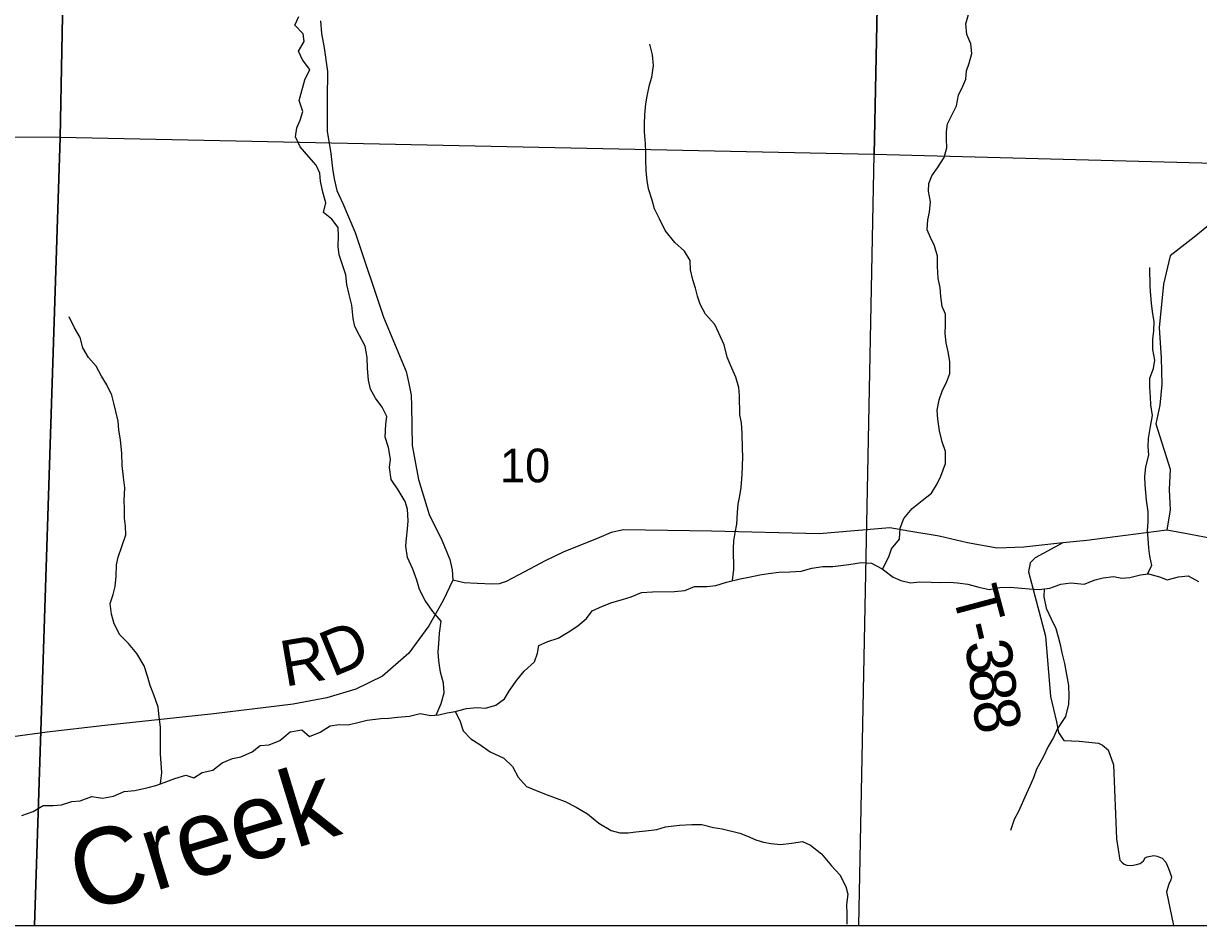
# Model space of a CAD drawing. Extents: x -3.6 to 34, y 0 to 32.8.
# Drawn here: x -1.871 to -0.41, y 26.043 to 27.165 of the extents above; entities that cross this region are included whole.
import ezdxf

# ---------------------------------------------------------------- set-up
doc = ezdxf.new("R2010")
doc.units = 0
for name, color, linetype in [('GM_X_Corporation', 7, 'Continuous'), ('GM_X_County_Road', 7, 'Continuous'), ('GM_X_County_Road_Text', 7, 'Continuous'), ('GM_X_Minor_River', 7, 'Continuous'), ('GM_X_Minor_River_Text', 7, 'Continuous'), ('GM_X_Section_Text', 7, 'Continuous'), ('GM_X_Township_Road', 7, 'Continuous'), ('GM_X_Township_Road_Text', 7, 'Continuous'), ('SH_Data', 7, 'Continuous')]:
    doc.layers.add(name, color=color, linetype=linetype)

msp = doc.modelspace()

# ---------------------------------------------------------------- linework, layer by layer
at = {"layer": 'GM_X_Corporation'}
for points in [[(3.1705, 28.9337), (3.1705, 32.8429), (-3.6295, 32.8429), (-3.6295, 26.0429), (2.3706, 26.0429), (2.3712, 26.0804), (2.3716, 26.1248), (2.3732, 26.2253), (2.3789, 26.6097), (2.3911, 27.5117), (2.3952, 27.9336), (2.3997, 28.282), (2.4082, 28.9473), (2.5416, 28.945), (2.5837, 28.9442), (2.8343, 28.9397)], [(-1.8056, 28.0368), (-1.8251, 27.0226), (-2.8456, 27.0298), (-2.8264, 28.0607)], [(-0.7925, 28.0131), (-0.8131, 27.0015), (-1.8251, 27.0226), (-1.8056, 28.0368)], [(-0.7925, 28.0131), (0.2336, 27.9902), (0.2053, 26.9746), (-0.8131, 27.0015)], [(-2.8578, 26.0429), (-1.8572, 26.0429), (-1.8251, 27.0226), (-2.8456, 27.0298)], [(-1.8572, 26.0429), (-0.8324, 26.0429), (-0.8131, 27.0015), (-1.8251, 27.0226)]]:
    msp.add_lwpolyline(points, close=True, dxfattribs=at)
msp.add_lwpolyline([(-0.398, 30.5946), (-0.453, 30.5952), (-0.5034, 30.5954), (-2.3541, 30.6318), (-2.7027, 30.634), (-2.8007, 30.6338), (-2.8012, 30.524), (-2.8047, 30.129), (-2.8073, 29.6484), (-2.813, 28.9119), (-2.8208, 28.0589), (-2.8426, 27.1), (-2.8499, 26.4099), (-2.8635, 26.0429), (2.3706, 26.0429)], dxfattribs=at)
at = {"layer": 'GM_X_County_Road'}
msp.add_lwpolyline([(-1.5014, 27.168), (-1.5002, 27.152), (-1.4969, 27.1342), (-1.4928, 27.105), (-1.4934, 27.0712), (-1.4934, 27.044), (-1.4932, 27.0308), (-1.4887, 27.003), (-1.4867, 26.9844), (-1.4847, 26.9713), (-1.4811, 26.957), (-1.4737, 26.9406), (-1.4582, 26.9046), (-1.4232, 26.7992), (-1.3951, 26.7317), (-1.3916, 26.7167), (-1.3889, 26.7025), (-1.3885, 26.6889), (-1.3875, 26.6396), (-1.3797, 26.5974), (-1.3665, 26.554), (-1.3503, 26.5214), (-1.3406, 26.4982), (-1.3378, 26.485), (-1.3369, 26.4723), (-1.3491, 26.447), (-1.3667, 26.4157), (-1.3915, 26.3814), (-1.4244, 26.353), (-1.4574, 26.3366), (-1.4937, 26.3258), (-1.5355, 26.3181), (-1.6342, 26.306), (-1.7694, 26.2915), (-1.8412, 26.2831), (-1.8841, 26.2773)], dxfattribs=at)
at = {"layer": 'GM_X_Minor_River'}
for points in [[(-0.7085, 27.0754), (-0.7029, 27.0868), (-0.6995, 27.0953), (-0.6985, 27.1055), (-0.6953, 27.1154), (-0.692, 27.1273), (-0.6933, 27.1394), (-0.6981, 27.1507), (-0.6994, 27.164), (-0.6951, 27.1785), (-0.6922, 27.1918), (-0.6955, 27.2066), (-0.7006, 27.2183), (-0.703, 27.2323), (-0.6975, 27.2453), (-0.694, 27.259), (-0.7009, 27.2709), (-0.7109, 27.2783)], [(-1.3576, 26.3046), (-1.3517, 26.319), (-1.3477, 26.3323), (-1.3487, 26.3441), (-1.3523, 26.3581), (-1.3544, 26.3721), (-1.3554, 26.3827), (-1.3544, 26.3937), (-1.3535, 26.4066), (-1.3515, 26.4215), (-1.3619, 26.4334), (-1.3712, 26.4469), (-1.3786, 26.4608), (-1.3818, 26.4722), (-1.3866, 26.4858), (-1.3933, 26.5004), (-1.3954, 26.5145), (-1.3944, 26.524), (-1.3935, 26.5357), (-1.3925, 26.546), (-1.3935, 26.5604), (-1.3963, 26.5702), (-1.4049, 26.5845), (-1.4138, 26.5973), (-1.4159, 26.6124), (-1.4146, 26.6227), (-1.4171, 26.6374), (-1.4211, 26.6503), (-1.4202, 26.6662), (-1.4192, 26.6757), (-1.4247, 26.6874), (-1.4333, 26.6987), (-1.4395, 26.7099), (-1.4419, 26.7209), (-1.4429, 26.7357), (-1.4435, 26.749), (-1.4461, 26.7633), (-1.4531, 26.7765), (-1.4589, 26.7878), (-1.461, 26.7976), (-1.4624, 26.8143), (-1.466, 26.8275), (-1.4689, 26.84), (-1.4702, 26.8518), (-1.4738, 26.8631), (-1.4782, 26.877), (-1.4795, 26.8873), (-1.479, 26.9006), (-1.4795, 26.9108), (-1.4873, 26.9213), (-1.4976, 26.9295), (-1.4948, 26.9417), (-1.4988, 26.9549), (-1.5013, 26.9685), (-1.5022, 26.9784), (-1.5069, 26.9885), (-1.5158, 26.9986), (-1.5266, 27.011), (-1.5325, 27.0234), (-1.5308, 27.0348), (-1.5268, 27.0444), (-1.5235, 27.055), (-1.5279, 27.0686), (-1.5208, 27.0946), (-1.5149, 27.1072), (-1.5238, 27.1195), (-1.5289, 27.1301), (-1.522, 27.142), (-1.5229, 27.1518), (-1.5333, 27.1623), (-1.5285, 27.1734)], [(-0.9894, 26.4718), (-0.9876, 26.4857), (-0.9881, 26.5115), (-0.9878, 26.5214), (-0.9861, 26.5313), (-0.984, 26.542), (-0.9831, 26.5564), (-0.9825, 26.5667), (-0.9801, 26.5773), (-0.9787, 26.5876), (-0.9775, 26.6039), (-0.9769, 26.6142), (-0.9767, 26.626), (-0.9769, 26.6358), (-0.9772, 26.6552), (-0.9782, 26.6681), (-0.9802, 26.6779), (-0.9806, 26.7018), (-0.9815, 26.7117), (-0.9851, 26.7249), (-0.9902, 26.7358), (-0.9958, 26.7498), (-0.9998, 26.7649), (-1.0065, 26.7796), (-1.0112, 26.7901), (-1.0228, 26.8032), (-1.0294, 26.8156), (-1.033, 26.8254), (-1.0354, 26.8356), (-1.0386, 26.8458), (-1.0415, 26.8583), (-1.042, 26.8697), (-1.049, 26.8813), (-1.0609, 26.8921), (-1.0729, 26.9071), (-1.08, 26.9218), (-1.0862, 26.9342), (-1.0891, 26.9448), (-1.0938, 26.9588), (-1.0955, 26.9694), (-1.0965, 26.9815), (-1.0971, 26.9944), (-1.0969, 27.005), (-1.0974, 27.0149), (-1.0988, 27.03), (-1.0986, 27.0399), (-1.0984, 27.0509), (-1.0971, 27.0646), (-1.0954, 27.0741), (-1.0926, 27.0882), (-1.0897, 27.0978), (-1.0877, 27.1122), (-1.089, 27.1255), (-1.0923, 27.1387)], [(-0.8027, 26.4858), (-0.7952, 26.5015), (-0.7916, 26.5111), (-0.7816, 26.5234), (-0.7811, 26.5371), (-0.7763, 26.5489), (-0.7659, 26.5616), (-0.7536, 26.5713), (-0.742, 26.5806), (-0.735, 26.5921), (-0.7306, 26.6017), (-0.7248, 26.6174), (-0.7247, 26.6322), (-0.7287, 26.6443), (-0.732, 26.6582), (-0.7341, 26.6726), (-0.735, 26.6836), (-0.7326, 26.6966), (-0.7286, 26.7073), (-0.7231, 26.7195), (-0.7191, 26.7291), (-0.7194, 26.7443), (-0.7211, 26.7564), (-0.7239, 26.7673), (-0.7252, 26.7791), (-0.7246, 26.7893), (-0.7245, 26.803), (-0.7288, 26.8128), (-0.7305, 26.8249), (-0.7311, 26.8363), (-0.7336, 26.8476), (-0.7345, 26.8624), (-0.7344, 26.8753), (-0.7384, 26.8882), (-0.7431, 26.8983), (-0.7474, 26.9081), (-0.7465, 26.9203), (-0.7444, 26.9298), (-0.7434, 26.9427), (-0.7456, 26.956), (-0.7453, 26.9655), (-0.7417, 26.975), (-0.7347, 26.985), (-0.7262, 26.9977), (-0.723, 27.0099), (-0.7232, 27.0209), (-0.7233, 27.0304), (-0.722, 27.0399), (-0.7172, 27.0498), (-0.711, 27.0621), (-0.7085, 27.0754)], [(-0.4737, 26.4802), (-0.4682, 26.4907), (-0.4707, 26.502), (-0.472, 26.5122), (-0.4725, 26.524), (-0.4734, 26.5335), (-0.4728, 26.5449), (-0.4726, 26.5574), (-0.4747, 26.5718), (-0.4765, 26.5908), (-0.477, 26.6014), (-0.4757, 26.6132), (-0.4718, 26.6277), (-0.4727, 26.6387), (-0.4724, 26.6486), (-0.4696, 26.6635), (-0.4672, 26.6772), (-0.4693, 26.6904), (-0.4698, 26.7003), (-0.4707, 26.7117), (-0.4705, 26.7235), (-0.4661, 26.7357), (-0.4644, 26.746), (-0.4668, 26.7592), (-0.4667, 26.7721), (-0.4657, 26.7824), (-0.4654, 26.7934), (-0.4671, 26.8063), (-0.4684, 26.8169), (-0.4693, 26.8264), (-0.4702, 26.8374), (-0.4706, 26.861)], [(-1.7002, 26.2193), (-1.6988, 26.2326), (-1.6994, 26.2448), (-1.7004, 26.2561), (-1.7002, 26.2671), (-1.7005, 26.2895), (-1.7019, 26.3024), (-1.7032, 26.3145), (-1.7088, 26.3296), (-1.7131, 26.3413), (-1.7167, 26.353), (-1.7207, 26.3658), (-1.7297, 26.3812), (-1.7401, 26.3936), (-1.7509, 26.4044), (-1.7579, 26.418), (-1.7615, 26.43), (-1.7629, 26.4433), (-1.7593, 26.4544), (-1.7568, 26.4643), (-1.7555, 26.4772), (-1.755, 26.4913), (-1.7529, 26.5008), (-1.7485, 26.5141), (-1.7435, 26.5286), (-1.7437, 26.5396), (-1.745, 26.5495), (-1.7452, 26.5613), (-1.7457, 26.5715), (-1.7448, 26.5871), (-1.7462, 26.6003), (-1.7479, 26.6151), (-1.7486, 26.6303), (-1.7503, 26.6466), (-1.7521, 26.6594), (-1.753, 26.6701), (-1.7559, 26.6821), (-1.7583, 26.6924), (-1.7607, 26.7022), (-1.767, 26.7154), (-1.7736, 26.7259), (-1.7802, 26.7383), (-1.7899, 26.7491), (-1.7969, 26.7612), (-1.8001, 26.774), (-1.8072, 26.786), (-1.8138, 26.7996)], [(-1.5764, 26.2666), (-1.5654, 26.2675), (-1.5519, 26.2731), (-1.5392, 26.2839), (-1.5248, 26.2861), (-1.5152, 26.2779), (-1.5021, 26.2834), (-1.4894, 26.2912), (-1.4784, 26.2929), (-1.467, 26.2924), (-1.4535, 26.2956), (-1.4433, 26.2984), (-1.4267, 26.3003), (-1.4165, 26.3008), (-1.4059, 26.3021), (-1.3908, 26.3031), (-1.3776, 26.3064), (-1.3643, 26.304), (-1.3545, 26.3049), (-1.3439, 26.3074), (-1.3341, 26.309), (-1.3201, 26.3127), (-1.3069, 26.3141), (-1.2963, 26.3131), (-1.2835, 26.3167), (-1.2726, 26.3249), (-1.2664, 26.3349), (-1.2575, 26.3479), (-1.2482, 26.3591), (-1.2356, 26.3707), (-1.2319, 26.3814), (-1.2302, 26.3909), (-1.2189, 26.396), (-1.2061, 26.4), (-1.1938, 26.4078), (-1.1818, 26.4156), (-1.171, 26.4245), (-1.1636, 26.4341), (-1.1508, 26.4401), (-1.1395, 26.4444), (-1.1259, 26.4481), (-1.1154, 26.4517), (-1.1026, 26.4568), (-1.0886, 26.4578), (-1.0614, 26.4583), (-1.0485, 26.4596), (-1.0365, 26.4644), (-1.0214, 26.4643), (-1.01, 26.4656), (-0.9968, 26.47), (-0.9799, 26.4741), (-0.9689, 26.4762), (-0.9554, 26.4791), (-0.9448, 26.4804), (-0.9316, 26.4821), (-0.9183, 26.4827), (-0.904, 26.4837), (-0.8908, 26.4874), (-0.8772, 26.4895), (-0.8647, 26.4893), (-0.8549, 26.4907), (-0.8447, 26.4916), (-0.8292, 26.4941), (-0.8167, 26.4936), (-0.8033, 26.4862), (-0.7895, 26.4762), (-0.78, 26.4718), (-0.7682, 26.469), (-0.7565, 26.4703), (-0.7425, 26.4698), (-0.7323, 26.4696), (-0.7198, 26.4698), (-0.7095, 26.4688), (-0.697, 26.4672)], [(-0.697, 26.4672), (-0.6832, 26.4638), (-0.6703, 26.4606), (-0.657, 26.4631), (-0.6442, 26.4637), (-0.6302, 26.4624), (-0.6207, 26.4614), (-0.6082, 26.4608), (-0.595, 26.4625), (-0.5814, 26.4673), (-0.569, 26.469), (-0.5523, 26.4673), (-0.5384, 26.4729), (-0.5286, 26.4753), (-0.5157, 26.477), (-0.5055, 26.4749), (-0.4953, 26.4758), (-0.4821, 26.4791), (-0.4723, 26.4803), (-0.4586, 26.4764), (-0.4491, 26.4727), (-0.4351, 26.4763), (-0.423, 26.4777), (-0.4101, 26.4707)], [(-0.602, 26.4616), (-0.6024, 26.4514), (-0.5995, 26.4374), (-0.5933, 26.4242), (-0.5874, 26.4121), (-0.5846, 26.4019), (-0.5822, 26.3921), (-0.5798, 26.3819), (-0.5766, 26.3686), (-0.5716, 26.3413), (-0.5711, 26.3281), (-0.5717, 26.3182), (-0.5756, 26.3029), (-0.5852, 26.288), (-0.5904, 26.2765), (-0.597, 26.2654), (-0.6033, 26.2524), (-0.6114, 26.2371), (-0.615, 26.2264), (-0.6198, 26.216), (-0.6245, 26.2061), (-0.634, 26.1847), (-0.6392, 26.1747), (-0.6439, 26.161)], [(-1.3341, 26.309), (-1.3282, 26.2978), (-1.3242, 26.2849), (-1.3146, 26.2748), (-1.3035, 26.2678), (-1.2905, 26.2589), (-1.2737, 26.2509), (-1.2629, 26.2404), (-1.2559, 26.2273), (-1.2455, 26.2157), (-1.2314, 26.2098), (-1.2196, 26.2055), (-1.2085, 26.2011), (-1.1975, 26.1971), (-1.1837, 26.1902), (-1.1696, 26.1817), (-1.1554, 26.1702), (-1.1401, 26.1609), (-1.1294, 26.1581), (-1.1192, 26.1579), (-1.1094, 26.1592), (-1.0973, 26.1605), (-1.0833, 26.1623), (-1.0728, 26.1655), (-1.0554, 26.1677), (-1.0399, 26.1683), (-1.0274, 26.1685), (-1.013, 26.1646), (-1.0023, 26.1629), (-0.9803, 26.1576), (-0.9708, 26.154), (-0.9605, 26.1496), (-0.951, 26.1467), (-0.9411, 26.145), (-0.9297, 26.1437), (-0.9161, 26.1454), (-0.9025, 26.1475), (-0.8922, 26.1428), (-0.8788, 26.132), (-0.8664, 26.117), (-0.856, 26.1058), (-0.8486, 26.0915), (-0.8462, 26.0817), (-0.8475, 26.0688), (-0.8473, 26.0574), (-0.8471, 26.0445)], [(-1.8728, 26.1796), (-1.8585, 26.1848), (-1.8461, 26.1922), (-1.8336, 26.192), (-1.8234, 26.1929), (-1.8106, 26.197), (-1.8004, 26.1979), (-1.7858, 26.2031), (-1.7725, 26.2014), (-1.7589, 26.2035), (-1.7454, 26.2095), (-1.7321, 26.2108), (-1.7159, 26.2145), (-1.7061, 26.2169), (-1.696, 26.2209), (-1.6824, 26.2257), (-1.6689, 26.2297), (-1.659, 26.2265), (-1.6485, 26.2331), (-1.6353, 26.236), (-1.6237, 26.2453), (-1.6109, 26.2504), (-1.6004, 26.2525), (-1.5865, 26.2588), (-1.5764, 26.2666)]]:
    msp.add_lwpolyline(points, dxfattribs=at)
at = {"layer": 'GM_X_Township_Road'}
for points in [[(-0.2946, 27.4589), (-0.2948, 27.449), (-0.3199, 27.0458), (-0.3252, 27.0119), (-0.3326, 26.985), (-0.3514, 26.9576), (-0.3819, 26.9261), (-0.4155, 26.8987), (-0.4454, 26.8755), (-0.4537, 26.8403), (-0.459, 26.7861), (-0.4566, 26.7489), (-0.4555, 26.7158), (-0.4583, 26.6899), (-0.4632, 26.6669), (-0.4453, 26.6102), (-0.4465, 26.5849), (-0.4455, 26.5596), (-0.4495, 26.5346)], [(-0.5788, 26.5186), (-0.6272, 26.5135), (-0.6604, 26.5122), (-0.6973, 26.5189), (-0.7325, 26.527), (-0.7702, 26.5334), (-0.7939, 26.5372), (-0.8815, 26.5298), (-1.0156, 26.5333), (-1.1249, 26.5348), (-1.1402, 26.5317), (-1.1557, 26.525), (-1.1998, 26.5072), (-1.2229, 26.496), (-1.2469, 26.483), (-1.2708, 26.4707), (-1.2794, 26.4676), (-1.288, 26.4674), (-1.3067, 26.4683), (-1.323, 26.4691), (-1.3369, 26.4723)], [(-0.4495, 26.5346), (-0.5138, 26.5263), (-0.549, 26.5215), (-0.5788, 26.5186)], [(-0.3941, 26.5242), (-0.4288, 26.5307), (-0.4495, 26.5346)], [(-0.5788, 26.5186), (-0.6131, 26.5002), (-0.6194, 26.4938), (-0.6215, 26.4826), (-0.6001, 26.4026), (-0.594, 26.3275), (-0.5868, 26.296), (-0.5842, 26.2828), (-0.5775, 26.273), (-0.5585, 26.2719), (-0.5345, 26.2695), (-0.5293, 26.2673), (-0.5225, 26.2614), (-0.5156, 26.2425), (-0.512, 26.1505), (-0.508, 26.1243), (-0.5065, 26.1228), (-0.5052, 26.1215), (-0.5025, 26.1193), (-0.4991, 26.1181), (-0.4933, 26.1175), (-0.4873, 26.1187), (-0.4827, 26.1201), (-0.4807, 26.1215), (-0.4783, 26.1232), (-0.4765, 26.1269), (-0.4741, 26.1281), (-0.4699, 26.1292), (-0.4657, 26.1298), (-0.4613, 26.1292), (-0.4553, 26.1265), (-0.4509, 26.1217), (-0.4474, 26.1137), (-0.4436, 26.1033), (-0.4443, 26.0996), (-0.4468, 26.0941), (-0.45, 26.0849), (-0.4412, 26.0429)]]:
    msp.add_lwpolyline(points, dxfattribs=at)
at = {"layer": 'SH_Data'}
msp.add_line((-3.6295, 26.0429), (3.1705, 26.0429), dxfattribs=at)

# ---------------------------------------------------------------- texts
at = {"layer": 'GM_X_County_Road_Text'}
for s, rotation, p in [('D', 22.3953, (-1.4868, 26.3513)), ('R', 9.6388, (-1.5459, 26.3397))]:
    msp.add_text(s, height=0.0568, rotation=rotation, dxfattribs=at).set_placement(p)
at = {"layer": 'GM_X_Minor_River_Text'}
msp.add_text('Creek', height=0.09472, rotation=16.9768, dxfattribs=at).set_placement((-1.796, 26.0584))
at = {"layer": 'GM_X_Section_Text'}
msp.add_text('10', height=0.04186, rotation=0, dxfattribs=at).set_placement((-1.2783, 26.594))
at = {"layer": 'GM_X_Township_Road_Text'}
for s, rotation, p in [('T', 284.9458, (-0.7169, 26.4566)), ('-', 283.135, (-0.706, 26.416)), ('3', 278.7877, (-0.7009, 26.3944)), ('8', 274.8559, (-0.6957, 26.3608)), ('8', 280.466, (-0.692, 26.3199))]:
    msp.add_text(s, height=0.0568, rotation=rotation, dxfattribs=at).set_placement(p)

doc.saveas('drawing.dxf')
